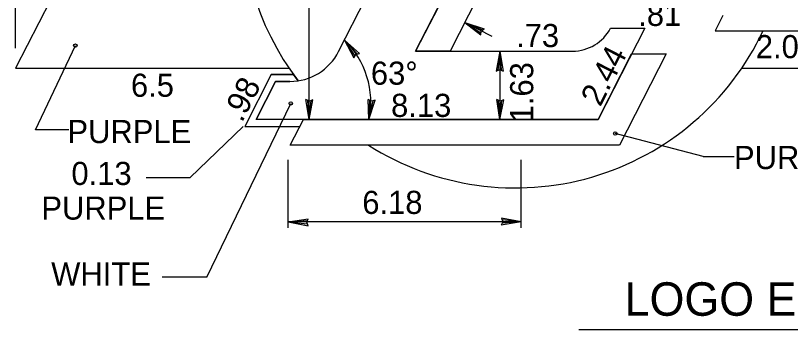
# Model space of a CAD drawing. Extents: x 10268197 to 10268826, y 2141503 to 2142677.
# Drawn here: x 10268779.93 to 10268799.84, y 2142357.53 to 2142365.61 of the extents above; entities that cross this region are included whole.
import ezdxf

# ---------------------------------------------------------------- set-up
doc = ezdxf.new("R2010")
doc.units = 0
for name, color, linetype in [('1', 7, 'Continuous'), ('21', 7, 'Continuous'), ('Default', 7, 'Continuous')]:
    doc.layers.add(name, color=color, linetype=linetype)

msp = doc.modelspace()

# ---------------------------------------------------------------- linework, layer by layer
at = {"layer": '1'}
for p, q in [((10268779.928, 2142364.767), (10268779.928, 2142377.787)), ((10268787.468, 2142362.931), (10268787.468, 2142373.475)), ((10268790.206, 2142364.688), (10268791.661, 2142367.544)), ((10268792.212, 2142366.884), (10268791.093, 2142364.688)), ((10268792.176, 2142365.066), (10268791.469, 2142365.426)), ((10268791.469, 2142365.426), (10268791.964, 2142365.266)), ((10268791.469, 2142365.426), (10268791.879, 2142365.106)), ((10268791.469, 2142365.426), (10268791.884, 2142365.158)), ((10268791.469, 2142365.426), (10268791.923, 2142365.234)), ((10268791.879, 2142365.106), (10268791.887, 2142365.205)), ((10268791.887, 2142365.205), (10268791.964, 2142365.266)), ((10268788.378, 2142364.972), (10268788.766, 2142364.625)), ((10268788.378, 2142364.972), (10268788.623, 2142364.514)), ((10268788.378, 2142364.972), (10268788.648, 2142364.559)), ((10268788.378, 2142364.972), (10268788.716, 2142364.612)), ((10268780.443, 2142362.666), (10268781.466, 2142364.83)), ((10268788.623, 2142364.514), (10268788.67, 2142364.6)), ((10268788.67, 2142364.6), (10268788.766, 2142364.625)), ((10268791.093, 2142364.688), (10268790.206, 2142364.688)), ((10268792.372, 2142364.688), (10268792.273, 2142364.178)), ((10268792.372, 2142364.688), (10268792.321, 2142364.197)), ((10268792.372, 2142364.688), (10268792.372, 2142362.931)), ((10268792.372, 2142364.688), (10268792.454, 2142364.174)), ((10268792.372, 2142364.688), (10268792.406, 2142364.196)), ((10268794.894, 2142362.931), (10268795.755, 2142364.62)), ((10268796.643, 2142364.62), (10268795.446, 2142362.271)), ((10268795.755, 2142364.62), (10268796.643, 2142364.62)), ((10268792.273, 2142364.178), (10268792.365, 2142364.215)), ((10268792.365, 2142364.215), (10268792.454, 2142364.174)), ((10268784.845, 2142358.882), (10268786.998, 2142363.345)), ((10268787.468, 2142362.931), (10268787.386, 2142363.444)), ((10268787.476, 2142363.403), (10268787.386, 2142363.444)), ((10268787.468, 2142362.931), (10268787.434, 2142363.423)), ((10268787.468, 2142362.931), (10268787.567, 2142363.441)), ((10268787.468, 2142362.931), (10268787.519, 2142363.422)), ((10268787.567, 2142363.441), (10268787.476, 2142363.403)), ((10268789.006, 2142362.931), (10268788.988, 2142363.45)), ((10268789.072, 2142363.399), (10268788.988, 2142363.45)), ((10268789.006, 2142362.931), (10268789.167, 2142363.426)), ((10268789.006, 2142362.931), (10268789.032, 2142363.423)), ((10268789.006, 2142362.931), (10268789.116, 2142363.412)), ((10268789.167, 2142363.426), (10268789.072, 2142363.399)), ((10268792.372, 2142362.931), (10268792.29, 2142363.444)), ((10268792.381, 2142363.403), (10268792.29, 2142363.444)), ((10268792.372, 2142362.931), (10268792.338, 2142363.423)), ((10268792.372, 2142362.931), (10268792.471, 2142363.441)), ((10268792.372, 2142362.931), (10268792.423, 2142363.422)), ((10268792.471, 2142363.441), (10268792.381, 2142363.403)), ((10268786.986, 2142362.271), (10268787.322, 2142362.931)), ((10268787.322, 2142362.931), (10268794.894, 2142362.931)), ((10268784.419, 2142361.442), (10268785.773, 2142362.754)), ((10268781.299, 2142362.666), (10268780.443, 2142362.666)), ((10268797.59, 2142361.982), (10268795.334, 2142362.572)), ((10268795.446, 2142362.271), (10268786.986, 2142362.271)), ((10268797.59, 2142361.982), (10268798.385, 2142361.982)), ((10268786.935, 2142360.149), (10268786.935, 2142361.895)), ((10268792.921, 2142360.149), (10268792.921, 2142361.895)), ((10268783.284, 2142361.442), (10268784.419, 2142361.442)), ((10268792.921, 2142360.298), (10268786.935, 2142360.298)), ((10268783.694, 2142358.89), (10268784.845, 2142358.89))]:
    msp.add_line(p, q, dxfattribs=at)
for centre in [(10268781.466, 2142364.831), (10268786.998, 2142363.346), (10268795.334, 2142362.572)]:
    msp.add_circle(centre, 0.0439, dxfattribs=at)
msp.add_arc((10268786.857, 2142363.386), 2.197, 348.03, 46.2026, dxfattribs=at)
at = {"layer": '21'}
for p, q in [((10268786.935, 2142360.298), (10268787.449, 2142360.379)), ((10268787.409, 2142360.29), (10268787.449, 2142360.379)), ((10268792.921, 2142360.298), (10268792.41, 2142360.397)), ((10268792.41, 2142360.397), (10268792.447, 2142360.305)), ((10268792.921, 2142360.298), (10268792.43, 2142360.349)), ((10268786.935, 2142360.298), (10268787.428, 2142360.332)), ((10268786.935, 2142360.298), (10268787.446, 2142360.199)), ((10268786.935, 2142360.298), (10268787.427, 2142360.246)), ((10268787.446, 2142360.199), (10268787.409, 2142360.29)), ((10268792.447, 2142360.305), (10268792.407, 2142360.216)), ((10268792.921, 2142360.298), (10268792.407, 2142360.216)), ((10268792.921, 2142360.298), (10268792.429, 2142360.263)), ((10268794.399, 2142357.533), (10268804.24, 2142357.533))]:
    msp.add_line(p, q, dxfattribs=at)
at = {"layer": 'Default'}
for p, q in [((10268788.227, 2142364.677), (10268791.873, 2142371.834)), ((10268791.661, 2142367.544), (10268790.206, 2142364.688)), ((10268790.206, 2142364.688), (10268791.661, 2142367.544)), ((10268792.212, 2142366.884), (10268791.093, 2142364.688)), ((10268780.824, 2142366.006), (10268779.928, 2142364.248)), ((10268798.095, 2142365.606), (10268797.898, 2142365.215)), ((10268796.091, 2142365.279), (10268794.894, 2142362.931)), ((10268795.212, 2142365.279), (10268796.091, 2142365.279)), ((10268797.898, 2142365.215), (10268800.094, 2142365.215)), ((10268790.206, 2142364.688), (10268794.237, 2142364.688)), ((10268791.093, 2142364.688), (10268790.206, 2142364.688)), ((10268794.894, 2142362.931), (10268795.755, 2142364.62)), ((10268796.643, 2142364.62), (10268795.446, 2142362.271)), ((10268795.755, 2142364.62), (10268796.643, 2142364.62)), ((10268779.928, 2142364.248), (10268786.957, 2142364.248)), ((10268798.581, 2142364.248), (10268820.349, 2142364.248)), ((10268786.498, 2142364.086), (10268785.821, 2142362.754)), ((10268786.498, 2142364.086), (10268787.072, 2142364.086)), ((10268786.108, 2142362.931), (10268786.606, 2142363.909)), ((10268786.606, 2142363.909), (10268786.108, 2142362.931)), ((10268786.975, 2142363.91), (10268786.606, 2142363.909)), ((10268786.606, 2142363.909), (10268786.975, 2142363.909)), ((10268794.894, 2142362.931), (10268786.108, 2142362.931)), ((10268786.986, 2142362.271), (10268787.322, 2142362.931)), ((10268787.322, 2142362.931), (10268794.894, 2142362.931)), ((10268785.821, 2142362.754), (10268787.232, 2142362.754)), ((10268795.446, 2142362.271), (10268786.986, 2142362.271))]:
    msp.add_line(p, q, dxfattribs=at)
msp.add_lwpolyline([(10268787.072, 2142364.086), (10268786.498, 2142364.086), (10268785.821, 2142362.754), (10268787.232, 2142362.754), (10268787.322, 2142362.931), (10268786.108, 2142362.931), (10268786.606, 2142363.909), (10268786.975, 2142363.909), (10268787.191, 2142363.926)], close=True, dxfattribs=at)
for centre, radius, start, end in [((10268792.77, 2142368.203), 7.03, 48.5904, 217.4725), ((10268792.77, 2142368.203), 7.03, 237.5383, 334.8493), ((10268794.237, 2142365.787), 1.098, 270, 332.5096), ((10268786.975, 2142365.316), 1.406, 270, 332.9991)]:
    msp.add_arc(centre, radius, start, end, dxfattribs=at)

# ---------------------------------------------------------------- texts
at = {"layer": '1'}
for s, height, p in [('.81', 0.5942, (10268795.924, 2142365.337)), ('.73', 0.5942, (10268792.787, 2142364.793)), ('2.03', 0.5942, (10268798.944, 2142364.508)), ('63°', 0.5942, (10268789.057, 2142363.826)), ('6.5', 0.5942, (10268782.894, 2142363.516)), ('8.13', 0.5942, (10268789.576, 2142362.998)), ('PURPLE', 0.5942, (10268781.263, 2142362.325)), ('PURPLE', 0.5942, (10268798.384, 2142361.657)), ('0.13', 0.5942, (10268781.365, 2142361.248)), ('PURPLE', 0.5942, (10268780.593, 2142360.357)), ('6.18', 0.5942, (10268788.836, 2142360.504)), ('WHITE', 0.5942, (10268780.845, 2142358.663)), ('LOGO EP-12', 0.8605, (10268795.575, 2142357.886))]:
    msp.add_text(s, height=height, dxfattribs=at).set_placement(p)
for s, rotation, p in [('2.44', 63, (10268794.949, 2142363.239)), ('1.63', 90, (10268793.227, 2142362.859)), ('.98', 63, (10268785.744, 2142362.833))]:
    msp.add_text(s, height=0.5942, rotation=rotation, dxfattribs=at).set_placement(p)

doc.saveas('drawing.dxf')
